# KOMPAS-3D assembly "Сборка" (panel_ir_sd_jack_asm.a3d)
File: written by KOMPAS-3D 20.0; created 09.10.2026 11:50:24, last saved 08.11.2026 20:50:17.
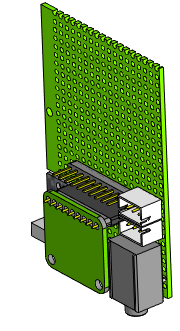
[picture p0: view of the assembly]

Document properties: Полное имя файла: D:\myProjects\Progect_esp32\box_compas\сборки компонентов\panel_ir_sd_jack_asm.a3d

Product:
- Part/product: Сборка
    Масса: 0.0629631
  - Component [detail]: Деталь  | Масса: 0.00128744; source file: ..\разъемы\pls_10.m3d
  - Component [detail]: Деталь  | Масса: 0.00276261; source file: ..\разъемы\pbs_9.m3d
  - Component [detail]: Деталь  | Масса: 0.0282233; source file: ..\макетки\Макетная плата_03.m3d
  - Component [detail]: Деталь  | Масса: 0.00363733; source file: ..\IR\ir_tzt.m3d
  - Component [detail]: Деталь  | Масса: 0.0149251; source file: ..\разъемы\PJ-306BM.m3d
  - Component [assembly]: Сборка  | Масса: 0.0097836; source file: ..\SD card\Adafruit_Micro_SD_SPI_or_SDIO asm.a3d
  - Component [detail]: Деталь  | qty 2  | Масса: 0.00117184; source file: ..\разъемы\B3B-XH-A.m3d

Referenced files in D:\myProjects\Progect_esp32\box_compas\макетки\: Макетная плата_03.m3d
Referenced files in D:\myProjects\Progect_esp32\box_compas\IR\: ir_tzt.m3d
Referenced files in D:\myProjects\Progect_esp32\box_compas\разъемы\: pbs_9.m3d, B3B-XH-A.m3d, PJ-306BM.m3d, pls_10.m3d
Referenced files in D:\myProjects\Progect_esp32\box_compas\SD card\: Adafruit_Micro_SD_SPI_or_SDIO asm.a3d
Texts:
  Деталь (1)
  Деталь (2)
